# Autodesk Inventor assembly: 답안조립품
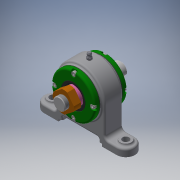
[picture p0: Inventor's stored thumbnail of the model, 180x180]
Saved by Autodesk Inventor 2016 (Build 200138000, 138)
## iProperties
Created: 2019-05
Part Number: 답안조립품
Material: 일반
Document SubType Name: Assembly
Designer: USER
Author: USER
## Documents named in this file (13)
- C:\Users\USER\Desktop\490504V1035\답안조립품.iam
- C:\Users\USER\Desktop\490504V1035\본체.ipt
- C:\Users\USER\Desktop\490504V1035\볼트 M4.ipt
- C:\Users\USER\Desktop\490504V1035\앵귤러 볼 베어링 7205.ipt
- C:\Users\USER\Desktop\490504V1035\오일 실 28 40 5 B.ipt
- C:\Users\USER\Desktop\490504V1035\축.ipt
- C:\Users\USER\Desktop\490504V1035\칼라.ipt
- C:\Users\USER\Desktop\490504V1035\커버.ipt
- C:\Users\USER\Desktop\490504V1035\개스킷.ipt
- C:\Users\USER\Desktop\490504V1035\그리스니플 M6.ipt
- 그리스니플  M6.ipt
- C:\Users\USER\Desktop\490504V1035\그리스니플개스킷.ipt
- C:\Users\USER\Desktop\490504V1035\베어링너트.ipt
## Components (4 placed, 3 different names)
1. 개스킷:1
2. 그리스니플개스킷:1
3. 개스킷:2
4. 그리스니플  M6:2
